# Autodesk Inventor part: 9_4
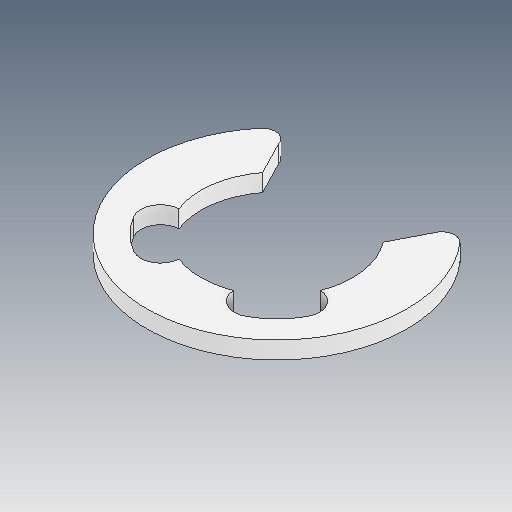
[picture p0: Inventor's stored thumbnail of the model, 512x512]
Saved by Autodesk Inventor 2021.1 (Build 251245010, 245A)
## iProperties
Created: 2021-06
Part Number: 9_4
Material: Ogólny
Document SubType Name: Modeling
Designer: user
Density: 1 g/cm^3
Appearance: Domyślna
Author: user
Revision Number: ÈÎºÎ
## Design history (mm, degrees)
feature "ÊäÈë1"
node "Bryła1"
